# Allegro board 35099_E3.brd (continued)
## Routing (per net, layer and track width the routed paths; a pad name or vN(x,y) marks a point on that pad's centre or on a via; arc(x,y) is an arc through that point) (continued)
P1_7_RST: length 171.8
  TOP w0.114: R144.3 v1(89.9,94.64) 92.18,94.64 TP42.1
  TOP w0.508: U32.4 v1(146.57,15.73)
  L3_IN1 w0.114: v1(76.71,25.53) 86.92,15.31 146.15,15.31 v1(146.57,15.73)
  L4_IN2 w0.114: v1(76.71,25.53) 77.92,26.74 84.62,26.74 98.39,40.51 99.31,40.51 102,43.2 102,50.95 98.44,54.51 98.44,69.27 102.21,73.04 102.21,74.69 101.27,75.64 99.1,75.64 94.11,80.62 94.11,89.58 92.61,91.08 92.61,91.94 v1(89.9,94.64)
P1_8: length 111.7
  TOP w0.114: v1(59.2,40.12) 44.92,40.12 J27.8 ; U18.B5 91.18,68.81 91.18,69.11 89.36,70.93 88.57,70.93 86.87,72.62 v1(86.87,73.13)
  L3_IN1 w0.114: v1(86.87,73.13) 76.28,73.13 73.83,70.68 64.2,70.68 50.67,57.15 34.95,57.15 J27.8
  BOTTOM w0.114: R209.1 R231.1 63.37,35.17 63.26,35.29 63.26,36.07 v1(59.2,40.12)
P1_9: length 78.8
  TOP w0.114: v1(72.9,73.18) 84.26,73.18 88.92,68.52 U18.B1 ; J28.1 27.43,60.29 29.11,61.97 43.65,61.97 45.05,63.36 50.66,63.36 52.98,65.67 52.98,70.01 v1(52.84,70.14)
  L3_IN1 w0.114: v1(72.9,73.18) 59.36,73.18 56.33,70.14 v1(52.84,70.14)
P1_10_MCLK: length 173.2
  TOP w0.114: U35.8 52.6,96.54 52.32,96.27 v1(52.32,95.81) 49.61,95.81 49.29,96.12 R403.1 ; v1(106.63,65) 105.1,65 104.62,64.52 U18.K16 ; TP8.1 v1(81.64,92.86)
  L3_IN1 w0.114: v1(81.64,92.86) 87.95,86.54 103.49,86.54 v1(103.51,86.53) ; J27.6 39.47,56.59 52.14,56.59 65.74,70.19 94.34,70.19 94.99,69.54 100.48,69.54 105.02,65 v1(106.63,65)
  L4_IN2 w0.114: v1(106.63,65) 106.64,65.02 106.64,83.39 v1(103.51,86.53)
  BOTTOM w0.114: v1(52.32,95.81) 52.73,95.4 65.08,95.4 67.62,92.86 v1(81.64,92.86)
P1_11_SPI_CLK: length 22.5
  TOP w0.114: U18.L2 89.71,63.77 86.07,63.77 85.12,62.82 72.35,62.82 72.03,62.51 72.03,59.68 71.43,59.08 R385.2
P1_11_SPI_CLK_A: length 161.5
  TOP w0.114: v1(64.67,62.09) 65.05,62.48 65.05,85.31 68.64,88.9 107.45,88.9 109.88,91.33 109.88,98.8 112.68,101.6 U4.13 ; R385.3 71.18,61.43 v1(71.14,61.46)
  L3_IN1 w0.114: v1(23.37,26.04) 22.86,26.54 22.86,34.54 23.5,35.18 33.02,35.18 54.23,56.39 56.52,56.39 61.78,61.66 70.95,61.66 v1(71.14,61.46)
  BOTTOM w0.114: R114.2 v1(23.37,26.04) ; v1(71.14,61.46) 70.51,62.09 v1(64.67,62.09)
P1_12_SPI_MISO: length 19.9
  TOP w0.114: U18.M2 86.17,63.52 85.22,62.58 74.9,62.58 73.81,61.49 73.81,59.68 73.21,59.08 R386.2
P1_12_SPI_MISO_A: length 152.8
  TOP w0.114: R386.3 72.95,61.43 v1(72.92,61.46) ; U26.7 110.94,96.21 110.37,95.64 110.37,91.08 107.72,88.42 68.84,88.42 65.53,85.11 65.53,63.9 v1(66.19,63.24)
  L3_IN1 w0.114: v1(33.02,33.91) 33.02,34.67 54.23,55.88 56.9,55.88 62.04,61.02 72.48,61.02 v1(72.92,61.46)
  BOTTOM w0.114: v1(33.02,33.91) 28.45,29.34 R112.2 ; v1(66.19,63.24) 66.82,62.6 71.78,62.6 v1(72.92,61.46)
P1_13_SPI_MOSI: length 14.6
  TOP w0.114: R387.2 76.82,59.08 79.84,62.1 85.42,62.1 86.35,63.02 U18.N1
P1_13_SPI_MOSI_A: length 162.3
  TOP w0.114: U4.11 113.5,102.6 113.49,102.61 112.06,102.61 108.98,99.53 108.98,91.17 107.2,89.39 68.44,89.39 64.14,85.08 64.14,66.27 63.14,65.27 63.14,60.42 v1(62.04,59.31) ; R387.3 76.51,61.55 v1(76.48,61.59)
  L3_IN1 w0.114: v1(23.37,30.99) 24.13,31.75 42.55,31.75 56.52,45.72 56.52,53.79 v1(62.04,59.31) 63.26,60.54 75.43,60.54 v1(76.48,61.59)
  BOTTOM w0.114: R111.2 v1(23.37,30.99)
P1_14_SPI_SS0: length 18.2
  TOP w0.114: U18.N2 89.71,63.28 86.27,63.28 85.32,62.34 76.31,62.34 75.59,61.62 75.59,59.68 74.99,59.08 R388.2
P1_14_SPI_SS0_A: length 177.3
  TOP w0.114: R388.3 74.73,61.43 v1(74.7,61.46) ; U4.14 112.56,101.1 110.13,98.67 110.13,91.18 107.62,88.66 68.74,88.66 65.29,85.21 65.29,61.7 59.22,55.63 58.17,55.63 56.52,53.98 56.52,47.24 v1(53.47,44.19)
  L3_IN1 w0.114: 53.47,44.19 53.47,51.31 57.15,54.99 57.15,55.34 62.59,60.78 74.02,60.78 v1(74.7,61.46) ; 53.47,44.19 v1(53.47,44.19) ; 53.47,44.19 42.17,32.89 24.77,32.89 v1(23.37,34.29)
  BOTTOM w0.114: R109.2 v1(23.37,34.29)
P1_15: length 72.3
  TOP w0.114: R86.2 JP13.3 137.44,51.15 SW5.6 ; v1(84.42,61.4) 84.87,61.86 85.52,61.86 86.43,62.77 90.21,62.77 U18.N3
  L3_IN1 w0.114: v1(84.42,61.4) 84.99,61.98 87.44,61.98 88.83,60.59 97.11,60.59 98.46,59.24 98.46,57.21 103.85,51.82 109.35,51.82 v1(111.38,53.85)
  L4_IN2 w0.114: JP13.3 129.88,54.7 129.41,54.23 116.84,54.23 116.46,53.85 v1(111.38,53.85)
P1_16: length 82.6
  TOP w0.114: R87.2 JP13.1 143.76,53.46 143.76,49.28 143,48.51 140.72,48.51 139.86,49.37 SW5.5 ; U18.M4 v2(90.47,63.52)
  L3_IN1 w0.114: v1(87.02,61.54) 87.54,61.54 88.7,60.38 96.98,60.38 98.08,59.28 98.08,55.46 102.18,51.36 v1(112.83,51.36)
  L4_IN2 w0.114: JP13.1 140.98,53.16 125.98,53.16 123.74,50.93 113.27,50.93 v1(112.83,51.36)
  BOTTOM w0.114: v1(87.02,61.54) 89,63.52 v2(90.47,63.52)
P1_17: length 66.2
  TOP w0.114: U18.N4 v2(90.97,62.52) ; SW5.4 142.4,52.83 141.02,54.2 141.02,55.57 v1(140.46,56.13) R88.2
  L3_IN1 w0.114: v2(90.97,62.52) 90.99,62.52 91.97,61.54 96.85,61.54 99.1,59.29 99.1,58.13 101.47,55.75 v1(109.73,55.75)
  L4_IN2 w0.114: v1(140.46,56.13) 141.22,55.37 141.22,54.23 140.41,53.41 125.42,53.41 124,51.99 112.47,51.99 109.73,54.74 v1(109.73,55.75)
P1_18_OSPI_CLK0: length 16.3
  TOP w0.114: v1(94.47,54.43) 94.47,58.4 93.73,59.14 93.73,61.27 U18.T9 ; R245.1 v1(89.36,54.32)
  L3_IN1 w0.114: v1(89.36,54.32) 88.29,54.32 88.14,54.17 88.14,54 88.3,53.84 90.54,53.84 91.13,54.43 v1(94.47,54.43)
P1_19_OSPI_SSEL0: length 27.7
  TOP w0.114: v1(90.53,59.31) 90.97,59.75 U18.T4 ; R247.1 R240.2 83.76,47.31 v1(84.2,47.75) ; R248.1 v1(80.53,58.31)
  L3_IN1 w0.114: v1(80.53,58.31) 81.53,59.31 v1(90.53,59.31)
  L4_IN2 w0.114: v1(84.2,47.75) 80.53,51.42 v1(80.53,58.31)
P1_20_OSPI_D0: length 16.5
  TOP w0.114: R243.2 v1(89.36,53.32) ; v1(92.17,53.37) 92.17,55.37 91.09,56.45 91.09,57.89 91.21,58.02 91.21,61.27 U18.T5
  L3_IN1 w0.114: v1(89.36,53.32) 87.67,53.32 87.5,53.15 87.5,52.99 87.67,52.82 91.62,52.82 v1(92.17,53.37)
P1_21_OSPI_D1: length 15.8
  TOP w0.114: R417.2 v1(89.36,51.32) ; U18.U5 91.47,57.94 91.33,57.79 91.33,56.55 92.61,55.27 92.61,52.92 92.33,52.64 v1(92.33,52.07)
  L3_IN1 w0.114: v1(92.33,52.07) 92.33,51.15 92.02,50.83 88.98,50.83 88.83,50.98 88.83,51.15 89,51.32 v1(89.36,51.32)
P1_22_OSPI_D2: length 18
  TOP w0.114: v1(92.03,56.81) 91.83,57.02 91.83,57.61 91.97,57.76 U18.P6 ; v1(81.53,58.31) R418.2
  L3_IN1 w0.114: v1(81.53,58.31) 82.03,57.81 85.96,57.81 86.96,56.81 v1(92.03,56.81)
P1_23_OSPI_D3: length 16.4
  TOP w0.114: R419.2 v1(85.53,57.31)
  TOP w0.127: U18.P7 92.22,62.27 92.22,57.25 92.84,56.63 v1(92.84,56.25)
  L3_IN1 w0.114: v1(85.53,57.31) 86.59,56.25 88.44,56.25 88.54,56.15 88.54,56.13 88.64,56.03 88.78,56.03 88.89,56.13 88.89,56.15 88.99,56.25 89.13,56.25 89.23,56.15 89.23,55.93 89.33,55.83 89.47,55.83 89.57,55.93 89.57,56.15 89.67,56.25 89.81,56.25 90.01,56.05 90.15,56.05 90.25,56.15 90.26,56.15 90.36,56.25 v1(92.84,56.25)
P1_24_OSPI_D4: length 17
  TOP w0.114: U18.T7 92.48,61.52 92.72,61.28 92.72,57.9 92.92,57.7 v1(92.92,57.52) ; R244.2 v1(83.53,58.31)
  L3_IN1 w0.114: v1(92.92,57.52) 91.46,57.52 91.36,57.62 91.36,57.74 91.26,57.84 91.12,57.84 91.02,57.74 91.02,57.62 90.92,57.52 90.77,57.52 90.67,57.62 90.67,57.9 90.57,58 90.43,58 90.33,57.9 90.33,57.62 90.23,57.52 90.09,57.52 89.99,57.62 89.99,57.76 89.89,57.86 89.75,57.86 89.65,57.76 89.65,57.62 89.55,57.52 89.4,57.52 89.3,57.62 89.3,57.76 89.2,57.86 89.06,57.86 88.96,57.76 88.96,57.62 88.86,57.52 88.72,57.52 88.62,57.62 88.27,57.62 88.17,57.52 88.03,57.52 87.93,57.62 87.59,57.62 87.49,57.52 86.82,57.52 86.03,58.31 v1(83.53,58.31)
P1_25_OSPI_D5: length 17.5
  TOP w0.114: v1(93.29,53.33) 93.29,56.53 92.48,57.34 92.48,61.02 U18.U7 ; R420.2 v1(89.36,52.32)
  L3_IN1 w0.114: v1(89.36,52.32) 87.58,52.32 87.45,52.19 87.45,51.93 87.57,51.82 91.44,51.82 92.95,53.33 v1(93.29,53.33)
P1_26_OSPI_D6: length 16.7
  TOP w0.114: R421.2 v1(89.36,50.32) ; v1(93.95,52.35) 94.03,52.43 94.03,57.55 93.22,58.36 93.22,61.64 92.84,62.02
  TOP w0.127: 92.84,62.02 U18.R7
  L3_IN1 w0.114: v1(93.95,52.35) 91.92,50.32 v1(89.36,50.32)
P1_27_OSPI_D7: length 16.4
  TOP w0.114: v1(93.34,50.93) 93.34,52.7 93.73,53.08 93.73,57.51 92.97,58.27 92.97,61.52 U18.T8 ; R422.2 89.19,49.32 89.19,49.31 v1(89.36,49.31)
  L3_IN1 w0.114: v1(89.36,49.31) 89.37,49.31 91.73,49.31 v1(93.34,50.93)
P1_28_OSPI_DQS: length 16
  TOP w0.114: v1(94.02,58.24) 93.47,58.78 U18.U9 ; R246.1 v1(82.53,58.31)
  L3_IN1 w0.114: v1(82.53,58.31) 83.15,58.93 89.42,58.93 89.68,58.67 93.59,58.67 v1(94.02,58.24)
P1_29_OSPI_B_SCK: length 49.5
  TOP w0.114: R352.1 61.54,44.87 62.21,44.2 78.74,44.2 80.64,46.1 v1(80.64,47.24) ; U18.U3 90.47,60.65 89.85,60.03 89.85,57 91.49,55.37 91.49,49.65 91.69,49.44 v1(91.69,48.64)
  L3_IN1 w0.114: v1(91.69,48.64) 91.69,48.13 90.34,46.78 81.11,46.78 v1(80.64,47.24)
P1_30_SD0_CLK: length 50.1
  TOP w0.114: v1(97.61,50.61) 96.03,52.19 96.03,57.52 94.21,59.34 94.21,62.28 U18.P10 ; R302.2 v1(118.51,33.77)
  L3_IN1 w0.114: v1(97.61,50.61) 99.37,50.61 103.35,46.64 103.35,46.48 103.17,46.3 103.17,46.13 103.33,45.97 103.49,45.97 103.67,46.15 103.83,46.15 103.99,45.99 103.99,45.83 103.81,45.65 103.81,45.49 103.97,45.33 104.14,45.33 104.32,45.51 104.48,45.51 104.64,45.35 104.64,45.18 104.46,45 104.46,44.84 104.62,44.68 104.78,44.68 104.96,44.86 105.13,44.86 105.29,44.7 105.29,44.54 105.11,44.36 105.11,44.19 105.27,44.03 105.43,44.03 105.61,44.21 105.77,44.21 105.93,44.05 105.93,43.89 105.75,43.71 105.75,43.55 105.91,43.39 106.08,43.39 106.26,43.57 106.42,43.57 106.58,43.41 106.58,43.24 106.4,43.06 106.4,42.9 106.56,42.74 106.72,42.74 106.9,42.92 107.07,42.92 107.23,42.76 107.23,42.6 107.05,42.42 107.05,42.26 107.21,42.09 107.37,42.09 107.55,42.27 107.71,42.27 107.87,42.11 107.87,41.95 107.69,41.77 107.69,41.61 107.85,41.45 108.02,41.45 108.2,41.63 108.36,41.63 108.52,41.47 108.52,41.3 108.34,41.12 108.34,40.96 108.5,40.8 108.66,40.8 108.84,40.98 109.01,40.98 109.17,40.82 109.17,40.66 108.99,40.48 108.99,40.32 109.15,40.15 109.31,40.15 109.49,40.34 109.65,40.34 109.81,40.17 109.81,40.01 109.63,39.83 109.63,39.67 109.79,39.51 109.96,39.51 110.14,39.69 110.3,39.69 116.21,33.77 v1(118.51,33.77)
P1_31_SD0_CMD: length 52.2
  TOP w0.114: v1(95.53,55.57) 95.53,57.69 93.97,59.24 93.97,61.52 U18.R9 ; v1(126.26,34.54) 126.26,34.21 126.7,33.77 R303.2
  L3_IN1 w0.114: v1(126.26,34.54) 126.26,37.39 120.24,43.41 119.27,43.41 119.16,43.29 119.16,43.14 119.05,43.03 118.82,43.03 118.7,43.14 118.7,43.29 118.59,43.41 118.36,43.41 118.25,43.29 118.25,43.14 118.13,43.03 117.9,43.03 117.79,43.14 117.79,43.29 117.67,43.41 117.45,43.41 117.33,43.29 117.33,43.14 117.22,43.03 116.99,43.03 116.87,43.14 116.87,43.29 116.76,43.41 116.53,43.41 116.42,43.29 116.42,43.14 116.3,43.03 116.07,43.03 115.96,43.14 115.96,43.29 115.85,43.41 115.62,43.41 115.5,43.29 115.5,43.14 115.39,43.03 115.16,43.03 115.05,43.14 115.05,43.29 114.93,43.41 110.39,43.41 108.71,45.09 106.38,45.09 95.9,55.57 v1(95.53,55.57)
P2_0_SD0_D0: length 51.9
  TOP w0.114: 95.11,62.02 95.22,61.91 95.22,59.7 98.12,56.8 98.12,49.99 97.38,49.25 v1(96.49,49.25) ; v1(113.92,33.02) 114.67,33.77 R301.2
  TOP w0.127: 95.11,62.02 U18.R11
  L3_IN1 w0.114: v1(113.92,33.02) 113.54,32.64 108.53,32.64 107.8,33.38 107.8,33.54 107.94,33.68 107.94,33.84 107.78,34 107.62,34 107.47,33.86 107.31,33.86 107.15,34.02 107.15,34.18 107.29,34.33 107.29,34.49 107.13,34.65 106.97,34.65 106.83,34.51 106.67,34.51 106.5,34.67 106.5,34.83 106.65,34.97 106.65,35.14 106.49,35.3 106.32,35.3 106.18,35.15 106.02,35.15 105.86,35.32 105.86,35.48 106,35.62 106,35.78 105.84,35.94 105.68,35.94 105.53,35.8 105.37,35.8 105.21,35.96 105.21,36.12 105.35,36.27 105.35,36.43 105.19,36.59 105.03,36.59 104.89,36.45 104.73,36.45 104.56,36.61 104.56,36.77 104.71,36.91 104.71,37.07 104.55,37.24 104.38,37.24 104.24,37.09 104.08,37.09 103.92,37.25 103.92,37.42 104.06,37.56 104.06,37.72 103.9,37.88 103.74,37.88 103.59,37.74 103.43,37.74 103.27,37.9 103.27,38.06 103.41,38.21 103.41,38.37 103.25,38.53 103.09,38.53 102.95,38.39 102.79,38.39 102.63,38.55 102.63,38.71 102.77,38.85 102.77,39.01 102.61,39.18 102.44,39.18 102.3,39.03 102.14,39.03 101.98,39.19 101.98,39.36 102.12,39.5 102.12,39.66 101.96,39.82 101.8,39.82 101.66,39.68 101.49,39.68 101.33,39.84 101.33,40 101.48,40.15 101.48,40.31 101.31,40.47 101.15,40.47 101.01,40.33 100.85,40.33 100.69,40.49 100.69,40.65 100.83,40.79 100.83,40.95 100.67,41.12 100.51,41.12 100.36,40.97 100.2,40.97 100.04,41.13 100.04,41.3 100.18,41.44 100.18,41.6 100.02,41.76 99.86,41.76 99.72,41.62 99.55,41.62 98.93,42.24 98.93,46.81 v1(96.49,49.25)
P2_1_SD0_D1: length 50.2
  TOP w0.114: v1(97.25,52.27) 97.25,56.99 94.73,59.51 94.73,61.27 U18.T11 ; v1(111.9,33.2) 112.48,33.77 R300.2
  L3_IN1 w0.114: v1(111.9,33.2) 111.28,33.83 109.45,33.83 106.93,36.35 106.93,36.51 107.29,36.87 107.29,37.03 107.13,37.19 106.97,37.19 106.61,36.83 106.45,36.83 106.29,36.99 106.29,37.16 106.65,37.52 106.65,37.68 106.48,37.84 106.32,37.84 105.96,37.48 105.8,37.48 105.64,37.64 105.64,37.8 106,38.16 106,38.32 105.84,38.49 105.68,38.49 105.32,38.13 105.15,38.13 104.99,38.29 104.99,38.45 105.35,38.81 105.35,38.97 105.19,39.13 105.03,39.13 104.67,38.77 104.51,38.77 104.35,38.93 104.35,39.1 104.71,39.46 104.71,39.62 104.54,39.78 104.38,39.78 104.02,39.42 103.86,39.42 103.7,39.58 103.7,39.74 104.06,40.1 104.06,40.26 103.9,40.43 103.74,40.43 103.38,40.07 103.22,40.07 103.05,40.23 103.05,40.39 103.41,40.75 103.41,40.91 103.25,41.07 103.09,41.07 102.73,40.71 102.57,40.71 102.41,40.87 102.41,41.04 102.77,41.4 102.77,41.56 102.6,41.72 102.44,41.72 102.08,41.36 101.92,41.36 101.76,41.52 101.76,41.68 102.12,42.04 102.12,42.2 101.96,42.37 101.8,42.37 101.44,42.01 101.28,42.01 101.11,42.17 101.11,42.33 101.47,42.69 101.47,42.85 101.31,43.01 101.15,43.01 100.79,42.65 100.63,42.65 99.57,43.71 99.57,47.45 96.98,50.04 96.98,52 v1(97.25,52.27)
P2_2_SD0_D2: length 51.2
  TOP w0.114: U18.U11 94.47,59.43 96.6,57.3 v1(96.6,55.95) ; R305.2 v1(130.84,33.77)
  L3_IN1 w0.114: v1(96.6,55.95) 97.06,55.95 104.4,48.62 112.04,48.62 114.43,46.23 119.3,46.23 130,35.53 130,34.61 v1(130.84,33.77)
P2_3_SD0_D3: length 49.9
  TOP w0.114: R304.2 129.07,33.77 128.52,34.32 v1(128.52,34.54) ; U18.T12 94.97,59.61 97.69,56.89 v1(97.69,54.68)
  L3_IN1 w0.114: v1(97.69,54.68) 106.19,46.18 113.44,46.18 114.76,44.86 119.84,44.86 128.93,35.76 128.93,34.95 v1(128.52,34.54)
P2_4_SD0_WR_PRT: length 68.5
  TOP w0.114: U18.T13 95.85,61.15 95.85,59.76 96.98,58.62 99.6,56 v1(99.6,55.45) TP21.1 ; R307.2 122.95,33.84 v1(122.32,34.47)
  L4_IN2 w0.114: v1(122.32,34.47) 122.32,34.02 124.24,32.09 124.24,28.65 122.46,26.87 109.38,26.87 99.48,36.78 99.48,37.92 103.79,42.24 103.79,51.25 v1(99.6,55.45)
P2_5_SD0_D4: length 10.7
  TOP w0.114: TP24.1 98.36,52.6 98.36,56.9 96.6,58.66 95.47,59.79 U18.U13
P2_6_SD0_D5: length 8.9
  TOP w0.114: U18.U15 96.47,59.81 100.66,55.62 100.66,55.4 TP25.1
P2_7_SD0_D6: length 12.1
  TOP w0.114: TP26.1 103.26,53.05 102.91,53.41 102.91,54.31 102.08,55.13 101.49,55.13 97.3,59.33 97.3,60.51 96.97,60.83 U18.U16
P2_8_SD0_D7: length 13.7
  TOP w0.114: TP14.1 105.3,54.34 104.02,55.62 101.69,55.62 97.78,59.53 97.78,60.72 U18.U17
P2_9_SD0_CD: length 70.4
  TOP w0.114: J32.10 v1(125.38,31.57) 125.38,33.21 R310.2 ; TP22.1 v1(101.12,53.04) 100.42,53.74 100.42,55.52 96.09,59.86 96.09,61.41 U18.R13
  L4_IN2 w0.114: v1(101.12,53.04) 103.17,50.99 103.17,42.5 98.85,38.18 98.85,36.52 109.12,26.24 122.72,26.24 125.38,28.9 v1(125.38,31.57)
P2_10_SD0_RST_N: length 42.5
  TOP w0.114: v1(120.54,34.47) 121.17,33.84 R306.2 ; v2(96.83,60.02) 96.83,60.65 96.72,60.76 96.72,61.27 U18.T15
  L3_IN1 w0.114: v2(96.83,60.02) 95.09,58.27 95.09,55.01 96.42,53.68 97.16,53.68 114.44,36.4 115.75,36.4 117.67,34.47 v1(120.54,34.47)
P2_11_SD0_VOLT: length 96
  TOP w0.102: U18.T16 96.97,61.4 97.22,61.15 97.22,60.92
  TOP w0.114: v1(103.78,53.16) TP23.1 102.72,55.38 101.59,55.38 97.54,59.43 97.54,60.61 97.22,60.92
  L4_IN2 w0.114: v1(103.78,53.16) 105.79,55.17 105.79,63.36 107.32,64.89 107.32,65.24 107.52,65.44 107.52,65.8 107.32,66 107.32,83.95 107.32,83.96 102.86,88.42 96.41,88.42 93.38,91.45 93.38,92.39 91.19,94.59 91.19,105.91 88.85,108.24 86.5,108.24 85.34,109.4 85.34,114.5 87.71,116.87 87.71,118.54 J1.1
P2_12: length 186.3
  TOP w0.114: v1(85.13,10.74) 85.47,11.09 85.47,37.85 v1(82.17,41.15) ; R131.2 TP33.1 ; U18.T3 90.22,61.27 90.22,60.74 88.53,59.05 88.53,58.7 v1(88.78,58.46)
  TOP w0.152: U24.13 v1(143.13,7.44) 143.13,6.13 TP33.1
  L3_IN1 w0.114: v1(143.13,7.44) 140.98,9.6 86.27,9.6 v1(85.13,10.74)
  L4_IN2 w0.114: 88.77,58.46 86.11,61.12 86.11,76.81 87.36,78.06 87.36,83.61 85.85,85.12 85.85,95.54 89.51,99.2 89.51,104.11 84.53,109.09 84.53,116.64 J1.4 ; 88.77,58.46 v1(88.78,58.46) ; 88.77,58.46 86.49,56.18 86.49,46.51 82.17,42.19 v1(82.17,41.15)
P2_13: length 64.9
  TOP w0.114: U18.T1 88.27,60.33 v1(88.03,60.33)
  L4_IN2 w0.114: J1.2 84.94,115.93 84.94,109.27 89.9,104.31 89.9,98 86.23,94.33 86.23,85.29 87.6,83.93 87.6,77.79 86.35,76.55 86.35,62.92 88.03,61.24 v1(88.03,60.33)
P2_14: length 71.3
  TOP w0.114: v1(73.66,72.69) 84.4,72.69 89.08,68.02 U18.C1
  L4_IN2 w0.114: J1.9 77.46,118.63 77.46,116.84 79.65,114.64 79.65,108.5 70.73,99.57 70.73,84.74 73.41,82.06 73.41,72.94 v1(73.66,72.69)
P2_15: length 71.5
  TOP w0.114: U18.E2 89.71,66.77 83.34,66.77 83.04,66.46 v1(75.32,66.46)
  L4_IN2 w0.114: v1(75.32,66.46) 75.32,66.87 74.48,67.71 74.48,82.83 71.62,85.68 71.62,99.99 80.24,108.61 80.24,115.85 J1.8
P2_16_PDM_CLK01: length 23.3
  TOP w0.114: U18.R1 88.74,62.02 87.13,60.41 87.13,58.02 90.28,54.87 90.28,48.9 86.8,45.41 86.8,44.14 87.61,43.33 R379.2
P2_17_PDM_CLK23: length 20.4
  TOP w0.114: U18.U1 87.61,59.17 87.61,58.22 90.77,55.07 90.77,48.44 90.26,47.93 90.26,44.23 91.16,43.33 R389.2
P2_17_PDM_CLK23_A: length 37.1
  TOP w0.114: J31.5 96.22,14.48 94.11,14.48 93.6,13.97 93.6,12.95 93.03,12.39 91.75,12.39 91.24,12.9 R389.3
P2_18_PDM_CLK45: length 22.7
  TOP w0.114: R390.2 89.38,43.33 88.7,44.01 88.7,46.91 90.53,48.74 90.53,54.97 87.37,58.12 87.37,60.31 88.83,61.77 89.72,61.77 U18.R2
P2_18_PDM_CLK45_A: length 34.4
  TOP w0.114: J31.7 93.59,12.15 91.36,12.15 90.81,12.7 90.81,40.47 R390.3
P2_19_PDM_CLK67: length 21.3
  TOP w0.114: U18.T2 89.72,61.27 89.72,60.92 87.86,59.06 87.86,58.32 91.01,55.17 91.01,48.28 92.2,47.09 92.2,44.07 92.94,43.33 R384.2
P2_19_PDM_CLK67_A: length 28.8
  TOP w0.114: J31.9 93.02,14.12 R384.3
P2_20_PDM_DATA01: length 21.3
  TOP w0.114: U18.U2 89.97,60.83 88.1,58.96 88.1,58.42 91.25,55.27 91.25,48.38 93.78,45.86 93.78,44.27 94.72,43.33 R380.2
P2_21_PDM_DATA23: length 21.8
  TOP w0.114: R393.2 96.5,43.33 95.65,44.17 95.65,45.82 91.73,49.75 91.73,55.47 90.09,57.1 90.09,59.93 90.72,60.56 90.72,61.62 90.47,61.87 U18.R3
P2_21_PDM_DATA23_A: length 34.4
  TOP w0.114: v1(96.58,16.89) R393.1
  BOTTOM w0.114: J31.6 96.09,12.06 96.09,13.76 94.11,15.75 94.11,16.26 94.74,16.89 v1(96.58,16.89)
P2_22_PDM_DATA45: length 27.4
  TOP w0.114: U18.P3 88.9,62.52 86.89,60.51 86.89,57.92 90.04,54.77 90.04,49 89.32,48.27 85.82,48.27 85.02,47.47 85.02,44.14 85.83,43.33 R391.2
P2_22_PDM_DATA45_A: length 39.4
  TOP w0.114: J31.8 93.7,9.72 89.44,9.72 88.27,10.9 88.27,39.45 R391.3
P2_23_PDM_DATA67: length 23
  TOP w0.114: R392.2 98.27,43.33 97.41,44.2 97.41,47.6 96.59,48.42 95.24,48.42 92.85,50.8 92.85,55.37 91.57,56.65 91.57,57.69 91.72,57.84 91.72,62.28 U18.P5
P2_23_PDM_DATA67_A: length 35.6
  TOP w0.114: v1(98.35,17.53) R392.3
  BOTTOM w0.114: J31.10 93.47,12.03 93.47,16.26 94.74,17.53 v1(98.35,17.53)
P2_24_SWO: length 50.3
  TOP w0.114: v1(100.35,97.02) 100.05,96.71 U7.12 ; v1(108.26,64.33) 107.78,63.85 107.29,63.85 107.21,63.77 97.23,63.77 U18.L16
  L4_IN2 w0.114: v1(108.26,64.33) 107.81,64.77 107.81,65.05 108,65.24 108,66 107.81,66.19 107.81,84.54 107.87,84.6 107.87,85.16 107.81,85.22 107.81,86.3 107.78,86.34 107.78,86.67 108.04,86.94 108.04,87.3 107.78,87.57 107.78,90.24 108.06,90.52 108.06,90.88 107.78,91.17 107.78,91.25 102,97.02 v1(100.35,97.02)
P2_25_SWD_CLK: length 49.3
  TOP w0.114: v1(107.47,64.35) 107.15,64.35 106.82,64.02 U18.L17 ; U7.4 96.96,95.51 96.34,94.89 v1(96.34,94.02)
  L4_IN2 w0.114: v1(96.34,94.02) 97.15,93.21 100.57,93.21 107.57,86.2 107.57,85.12 107.63,85.06 107.63,84.7 107.57,84.64 107.57,66.09 107.76,65.9 107.76,65.34 107.57,65.15 107.57,64.46 v1(107.47,64.35)
P2_26_SWDIO: length 136.2
  TOP w0.114: v1(105.54,64.54) 105.28,64.28 96.72,64.28 U18.L15 ; v1(100.59,105.96) 98.97,105.96 96.9,108.03 JP19.1 98.53,111.3 107.98,111.3 v1(110.53,113.86) 110.74,114.07 J2.2 ; v1(101.26,87.05) 101.14,87.18 73.08,87.18 v1(71.25,85.35) J19.2 ; SH14.1 v1(75.77,107.95)
  L3_IN1 w0.114: v1(75.77,107.95) 82.07,107.95 82.57,108.45 95.68,108.45 JP19.1
  L4_IN2 w0.114: v1(105.54,64.54) 105.54,65.9 105.98,66.35 105.98,81.73 101.26,86.46 v1(101.26,87.05)
  BOTTOM w0.114: v1(101.26,87.05) 101.26,93.14 101.49,93.36 101.49,100.09 100.38,101.2 100.38,105.75 v1(100.59,105.96) ; D13.5 110.15,115.42 110.53,115.04 v1(110.53,113.86) ; R105.2 v1(71.25,85.35)
P2_27_USB1_OVERCURRENTN: length 76.3
  TOP w0.114: U13.A2 126.69,67.99 v1(125.76,67.99) ; U18.M14 107.41,63.52 v1(107.6,63.33) 108.74,63.33 111.1,65.7 111.1,73.81 109.69,75.22 107.14,75.22 104.31,78.05 97.86,78.05 R133.2
  L3_IN1 w0.114: v1(107.6,63.33) 122.51,63.33 125.76,66.57 v1(125.76,67.99)
P2_28_USB1_PWRENA: length 64.6
  TOP w0.114: v1(127.37,68.01) 130.8,71.44 Q1.1 ; R383.2 v1(102.02,82.19) ; U18.N15 96.73,63.28 106.62,63.28 v1(107.22,62.68)
  L3_IN1 w0.114: v1(127.37,68.01) 127.37,66.91 123.15,62.7 107.24,62.7 v1(107.22,62.68)
  L5_PWR w0.114: v1(107.22,62.68) 106.33,63.58 106.33,64.51 105.45,65.4 105.45,78.76 v1(102.02,82.19)
P2_29_I3C0_SCL: length 204.7
  TOP w0.114: v1(83.19,33.15) 81.66,33.15 R423.1 ; v1(98.68,90.21) 98.18,89.7 82.29,89.7 v1(82.17,89.83) 69.71,89.83 68.3,91.24 49.28,91.24 TP7.1 ; TP7.1 v1(48.64,90.7) ; TP7.1 47.64,92.87 47.64,94.42 47.85,94.63 47.85,99.11 49.85,101.11 R406.1 50.91,100.77 52.01,100.77 R409.2 U36.1 ; U18.N17 97.7,62.79 102.71,62.79 v1(102.76,62.84) ; R413.2 101.24,84.51 J18.1
  TOP w0.152: v1(49.71,76.67) 49.61,76.58 46.34,76.58 U12.A6 ; v1(49.44,64.69) 47.31,64.69 45.95,66.06 U17.A6
  L4_IN2 w0.114: v1(102.76,62.84) 102.76,63.82 105.5,66.56 105.5,80.24 J18.1 ; v1(82.17,89.83) 82.17,79.38 84.96,76.58 84.96,64.92 83.68,63.64 83.68,59.83 84.09,59.42 84.09,49.76 84.71,49.15 84.71,45.48 80.52,41.29 80.52,36.7 83.19,34.04 v1(83.19,33.15)
  L4_IN2 w0.152: v1(48.64,90.7) 49.71,89.64 v1(49.71,76.67) 49.71,64.96 v1(49.44,64.69)
  BOTTOM w0.114: J18.1 99.36,86.38 99.36,89.53 v1(98.68,90.21)
P2_30_I3C0_SDA: length 159.7
  TOP w0.114: J18.2 R414.2 R118.1 R405.1 ; v1(104.34,62.44) 104.02,62.13 102.51,62.13 102.36,62.27 97.22,62.27 U18.P16 ; v1(96.98,90.19) 96.74,90.42 70.06,90.42 68.75,91.74 50.85,91.74 v1(49.4,93.19) TP6.1 48.11,94.48 48.11,97.68 49.37,98.93 59.02,98.93 59.71,99.62 59.71,101.43 59.28,101.85 58.56,101.85 R410.2 U36.8
  TOP w0.152: U17.B6 46,65.6 46.01,65.6 47.66,63.95 v1(49.43,63.95) ; U12.B6 46.35,76.17 v1(50.32,76.17)
  L4_IN2 w0.114: J18.2 98.94,86.27 100.85,86.27 105.74,81.38 105.74,66.46 104.34,65.06 v1(104.34,62.44)
  L4_IN2 w0.152: v1(49.4,93.19) 50.32,92.27 v1(50.32,76.17) 50.32,64.83 v1(49.43,63.95)
  BOTTOM w0.114: J18.2 98.91,86.25 98.91,88.26 v1(96.98,90.19)
P2_31_I3C0_PUR: length 29.6
  TOP w0.114: R118.2 J18.3 ; v1(86.62,82.97) 86.27,82.97 86.06,82.76 86.06,75.31 88.03,73.35 88.03,72.49 88.87,71.65 89.72,71.65 91.97,69.4 U18.B6
  BOTTOM w0.114: J18.3 93.74,83.62 87.27,83.62 v1(86.62,82.97)
PDM_CLK01_EXT: length 41.7
  TOP w0.114: J31.3 98.4,11.88 89.46,11.88 88.75,12.6 88.75,40.75 R379.3
PDM_CLK01_ONBOARD: length 151.3
  TOP w0.114: v1(98.96,39.49) 99.31,39.13 99.31,34.5 105.05,28.76 105.05,8.71 104.52,8.18 103.78,8.18 103.24,7.65 U41.4 103.24,7.23 102.87,6.86 100.2,6.86 98.17,8.89 57.54,8.89 52.46,3.81 12.32,3.81 11.83,4.3 11.83,5.77 10.56,7.04 8.82,7.04 8.6,6.82 U40.4 ; v1(87.69,45.68) R379.1
  BOTTOM w0.114: v1(98.96,39.49) 93.88,39.49 v1(87.69,45.68)
PDM_DATA01_EXT: length 34.1
  TOP w0.114: R380.3 v1(94.8,16.26)
  BOTTOM w0.114: J31.4 98.63,12.06 98.63,14.14 96.52,16.26 v1(94.8,16.26)
PDM_DATA01_ONBOARD: length 144.6
  TOP w0.114: R380.1 v1(94.8,45.82) ; U40.1 7.78,3.92 7.89,3.81 9.25,3.81 10.14,2.92 52.7,2.92 57.91,8.13 97.92,8.13 100.22,5.83 101.72,5.83 ; 101.72,5.83 v1(101.7,5.84) ; 101.72,5.83 U41.1 ; v1(99.31,33.18) 104.14,28.34 v1(104.14,10.79)
  L3_IN1 w0.114: v1(99.31,33.18) 94.8,37.69 v1(94.8,45.82)
  BOTTOM w0.114: v1(101.7,5.84) 102.38,6.52 102.38,9.04 v1(104.14,10.79)
PIO0_7-FC1_SCK: length 37
  TOP w0.114: U18.J2 89.71,65.28 84.26,65.28 83.01,64.03 73.66,64.03 v1(72.67,65.02) ; R394.2 v1(57.67,58.67)
  L3_IN1 w0.114: v1(72.67,65.02) 70.44,62.79 61.79,62.79 v1(57.67,58.67)
PIO0_8-FC1_TXD_SCL_MISO: length 36.2
  TOP w0.114: U18.K4 85.8,64.52 84.82,63.54 70.07,63.54 v1(69.11,64.51) ; R395.2 57.67,61.34 v1(58.44,60.57)
  L3_IN1 w0.114: v1(58.44,60.57) 61.56,63.68 68.29,63.68 v1(69.11,64.51)
PIO0_10-FC1_CTS_SDA_SSELN0: length 33.7
  TOP w0.114: R396.2 84.05,43.33 83.37,44.01 83.37,46.16 85.72,48.51 89.22,48.51 89.8,49.1 89.8,54.67 86.65,57.82 86.65,59.94 v1(85.17,61.42) ; v1(85.17,64.51) 85.42,64.77 90.21,64.77 U18.J3
  L4_IN2 w0.114: v1(85.17,61.42) v1(85.17,64.51)
PIO0_14-FC2_SCK: length 46.2
  TOP w0.114: v1(69.62,72.38) 69.62,73.59 70.69,74.67 79.33,74.67 80.98,76.32 82.49,76.32 88.36,70.45 89.05,70.45 U18.A3 ; v1(56.92,64.13) 57.67,63.37 R397.2
  L3_IN1 w0.114: v1(69.62,72.38) 60.6,72.38 56.92,68.7 v1(56.92,64.13)
PIO0_31-FC4_CTS_SDA_SSELN0: length 45.6
  TOP w0.114: U18.A11 94.47,71.18 93.48,72.18 v1(93.22,72.18) ; R398.2 v1(57.67,68.32)
  L3_IN1 w0.114: v1(93.22,72.18) 90.64,72.18 89.04,73.78 76.59,73.78 73.73,70.92 60.27,70.92 v1(57.67,68.32)
QSPI_B_CS0: length 33.8
  TOP w0.114: R350.1 v1(64.54,47.82) 64.03,47.31 R364.2 ; v1(92.94,45.8) 93.02,45.71 R384.1
  L3_IN1 w0.114: v1(92.94,45.8) 92.35,45.21 67.14,45.21 v1(64.54,47.82)
  BOTTOM w0.254: R66.2 65.05,47.31 v1(64.54,47.82)
QSPI_B_DATA0: length 29.7
  TOP w0.114: R385.1 72.22,56.52 73.41,56.52 74.3,55.63 74.3,55.07 74.18,54.96 72.48,54.96 72.37,54.84 72.37,54.61 72.48,54.5 74.18,54.5 74.3,54.38 74.3,54.16 74.18,54.04 73.77,54.04 73.66,53.93 73.66,53.7 73.77,53.58 74.18,53.58 74.3,53.47 74.3,53.24 74.18,53.13 73.77,53.13 73.66,53.01 73.66,52.78 73.77,52.67 74.18,52.67 74.3,52.55 74.3,52.33 74.18,52.21 73.77,52.21 73.66,52.1 73.66,51.87 73.77,51.75 74.18,51.75 74.3,51.64 74.3,51.41 74.18,51.3 73.77,51.3 73.66,51.18 73.66,50.95 73.77,50.84 74.18,50.84 74.3,50.73 74.3,50.5 74.18,50.38 73.78,50.38 73.66,50.27 73.66,50.04 73.78,49.93 74.18,49.93 74.3,49.81 74.3,49.58 74.18,49.47 73.77,49.47 73.66,49.35 73.66,49.13 73.77,49.01 74.18,49.01 74.3,48.9 74.3,48.26 74.04,48.01 73.41,48.01 73.15,48.26 73.15,52.96 72.8,53.32 R354.1
QSPI_B_DATA1: length 34.1
  TOP w0.114: R386.1 74.68,55.83 74.68,47.88 74.29,47.5 73.41,47.5 72.26,48.64 72,48.64 71.88,48.53 71.88,47.23 71.77,47.12 71.54,47.12 71.42,47.23 71.42,48.53 71.31,48.64 71.08,48.64 70.97,48.53 70.97,47.23 70.85,47.12 70.62,47.12 70.51,47.23 70.51,48.53 70.4,48.64 70.17,48.64 70.05,48.53 70.05,47.23 69.94,47.12 69.71,47.12 69.6,47.23 69.6,48.53 69.48,48.64 69.25,48.64 69.14,48.53 69.14,47.23 69.02,47.12 68.8,47.12 68.68,47.23 68.68,48.53 68.57,48.64 68.34,48.64 68.22,48.53 68.22,47.23 68.11,47.12 67.88,47.12 67.77,47.23 67.77,48.53 67.65,48.64 67.37,48.64 R355.1
QSPI_B_DATA2: length 15.9
  TOP w0.114: R71.1 R356.1 v1(64.54,58.32) ; R387.1 76.39,57.56 v1(75.64,58.31)
  L3_IN1 w0.114: v1(64.54,58.32) 66.52,60.3 73.65,60.3 v1(75.64,58.31)
QSPI_B_DATA3: length 34.4
  TOP w0.114: R357.1 v1(66.54,58.32) ; R388.1 74.61,57.56 v1(73.85,58.32)
  L3_IN1 w0.114: v1(73.85,58.32) 73.85,59.76 73.55,60.06 73.28,60.06 73.17,59.94 73.17,58.53 73.05,58.42 72.82,58.42 72.71,58.53 72.71,59.94 72.59,60.06 72.36,60.06 72.25,59.94 72.25,58.53 72.14,58.42 71.91,58.42 71.79,58.53 71.79,59.94 71.68,60.06 71.45,60.06 71.34,59.94 71.34,58.53 71.22,58.42 70.99,58.42 70.88,58.53 70.88,59.94 70.76,60.06 70.54,60.06 70.42,59.94 70.42,58.53 70.31,58.42 70.08,58.42 69.96,58.53 69.96,59.94 69.85,60.06 69.62,60.06 69.51,59.94 69.51,58.45 69.39,58.33 69.16,58.33 69.05,58.45 69.05,59.92 68.94,60.04 68.71,60.04 68.59,59.92 68.59,58.53 68.48,58.42 68.25,58.42 68.14,58.53 68.14,59.94 68.02,60.06 67.79,60.06 67.68,59.94 67.68,58.53 67.56,58.42 67.34,58.42 67.22,58.53 67.22,59.94 67.11,60.06 66.62,60.06 65.91,59.35 65.91,58.94 v1(66.54,58.32)
QSPI_B_DATA4: length 34.9
  TOP w0.114: R389.1 91.24,47.21 v1(90.7,47.75) ; R358.1 v1(65.54,58.32)
  L3_IN1 w0.114: v1(65.54,58.32) 66.53,57.33 76.91,57.33 80.01,54.23 85.47,54.23 86.49,53.21 86.49,51.07 89.13,48.43 90.02,48.43 v1(90.7,47.75)
QSPI_B_DATA5: length 30.9
  TOP w0.114: R359.1 v1(71.24,52.32) ; v1(89.69,47.28) 89.46,47.06 R390.1
  L3_IN1 w0.114: v1(89.69,47.28) 89.49,47.28 87.55,49.22 82.29,49.22 82.17,49.1 82.17,48.76 82.06,48.64 81.83,48.64 81.71,48.76 81.71,49.1 81.6,49.22 81.37,49.22 81.26,49.1 81.26,48.76 81.14,48.64 80.91,48.64 80.8,48.76 80.8,49.1 80.69,49.22 80.46,49.22 80.34,49.1 80.34,48.76 80.23,48.64 80,48.64 79.89,48.76 79.89,49.1 79.77,49.22 79.54,49.22 79.43,49.1 79.43,48.76 79.31,48.64 79.09,48.64 78.97,48.76 78.97,49.1 78.86,49.22 78.63,49.22 78.51,49.1 78.51,48.76 78.4,48.64 78.17,48.64 78.06,48.76 78.06,49.1 77.94,49.22 77.71,49.22 77.6,49.1 77.6,48.76 77.49,48.64 77.26,48.64 77.14,48.76 77.14,49.1 77.03,49.22 76.8,49.22 76.69,49.1 76.69,48.76 76.57,48.64 76.34,48.64 76.23,48.76 76.23,49.1 76.11,49.22 75.89,49.22 75.77,49.1 75.77,48.76 75.66,48.64 75.43,48.64 75.31,48.76 75.31,49.1 75.2,49.22 74.34,49.22 v1(71.24,52.32)
QSPI_B_DATA6: length 27
  TOP w0.114: R360.1 v1(71.24,50.32) ; R391.1 85.72,45.04 v1(85.72,47.55)
  L3_IN1 w0.114: v1(85.72,47.55) 85.02,48.26 80.26,48.26 79.63,47.63 79.63,47.1 79.52,46.99 79.29,46.99 79.18,47.1 79.18,47.63 79.06,47.75 78.83,47.75 78.72,47.63 78.72,47.1 78.6,46.99 78.38,46.99 78.26,47.1 78.26,47.63 78.15,47.75 77.92,47.75 77.8,47.63 77.8,47.1 77.69,46.99 77.46,46.99 77.35,47.1 77.35,47.63 77.23,47.75 77,47.75 76.89,47.63 76.89,47.1 76.78,46.99 76.55,46.99 76.43,47.1 76.43,47.63 76.32,47.75 76.09,47.75 75.98,47.63 75.98,47.1 75.86,46.99 75.63,46.99 75.52,47.1 75.52,47.63 75.4,47.75 75.18,47.75 75.06,47.63 75.06,47.1 74.95,46.99 74.72,46.99 74.6,47.1 74.6,47.63 74.49,47.75 73.81,47.75 v1(71.24,50.32)
QSPI_B_DATA7: length 30.2
  TOP w0.114: R392.1 v1(98.35,45.85) ; R361.1 v1(71.29,49.32)
  L3_IN1 w0.114: v1(71.29,49.32) 74.34,46.26 97.94,46.26 v1(98.35,45.85)
QSPI_B_DQS: length 1.6
  TOP w0.114: TP44.1 R353.1
RESET_AMP: length 25.6
  TOP w0.152: v2(44.34,80.34) U12.E1 ; U17.E1 44.34,68.75 v2(44.33,68.76) 45.22,69.65 50.72,69.65 51.17,69.2 U16.4
  L4_IN2 w0.152: v2(44.34,80.34) 44.04,80.64 41.87,80.64 41.26,80.03 41.26,73.58 44.33,70.51 v2(44.33,68.76)
RESET_FXO: length 40.5
  TOP w0.114: v1(84.99,94.61) 85.02,94.64 R144.1 ; U30.4 v1(53.62,84.46)
  BOTTOM w0.114: v1(53.62,84.46) 56.68,84.46 58.2,85.98 58.2,90.62 58.84,91.26 62.14,91.26 62.98,92.1 82.48,92.1 v1(84.99,94.61)
RST_AP: length 4.4
  TOP w0.114: U108.A4 R242.1 77.53,53.32 R241.2
RST_MX: length 3
  TOP w0.114: R351.2 U19.A4
RTCXIN: length 6.6
  TOP w0.114: Y3.2 102.95,68.02 101.83,69.14 101.07,69.14 C69.1 99,68.63 98.89,68.52 U18.B17
RTCXOUT: length 6.9
  TOP w0.114: Y3.1 103,70.52 101.91,69.42 101.06,69.42 C62.1 99.66,69.02 U18.A17
SCL: length 52
  TOP w0.114: U18.E16 97.26,66.74 97.82,66.74 98.33,67.26 v1(104.94,67.26) TP30.1
  TOP w0.203: R84.2 125.7,48.69 v1(125.55,48.84) 125.43,48.97 124.19,48.97 123.96,49.2 U20.5
  BOTTOM w0.114: v1(125.55,48.84) 125.55,47.95 124.08,46.48 114.57,46.48 112.05,49 109.61,49 109.12,49.49 109.12,64.92 106.78,67.26 v1(104.94,67.26)
SCL_CODEC: length 16.4
  TOP w0.114: v1(49.81,100.09) R406.2 50.85,100.38 52.06,100.38 R411.2 U36.4
  TOP w0.152: v1(44.12,92.58) 44.12,93.64 43.76,94 U8.2
  L3_IN1 w0.114: v1(49.81,100.09) 49.26,100.09 44.12,94.96 v1(44.12,92.58)
SCLK_AP: length 7.4
  TOP w0.114: U108.B2 82.03,51.82 82.53,51.82 84.03,53.32 84.03,53.44 84.41,53.82 87.13,53.82 R245.2
SCLK_MX: length 3.8
  TOP w0.114: U19.B2 61.54,49.32 R352.2
SD_CLK: length 2
  TOP w0.114: J32.5 R302.1
SD_CMD: length 4.6
  TOP w0.114: J32.2 R303.1 126.92,32.25 125.6,33.57 R309.2
SD_DAT0: length 2.1
  TOP w0.114: J32.7 114.81,30.39 R301.1
SD_DAT1: length 2
  TOP w0.114: R300.1 112.95,32.24 J32.8
SD_DAT2: length 2
  TOP w0.114: J32.9 R305.1
SD_DAT3: length 2
  TOP w0.114: J32.1 R304.1
SD_RST_N: length 23.4
  TOP w0.114: R123.2 R90.1 U23.3 102.77,34.71 103.52,33.96 109.87,33.96 112.16,36.25 118.25,36.25 118.63,36.63 120.16,36.63 R306.1
SDA: length 56.5
  TOP w0.114: U18.F16 97.97,66.52 98.39,66.94 103.72,66.94 v1(104.05,66.62) 106.33,66.62 TP31.1
  TOP w0.203: R83.2 126.26,48.48 v1(126.26,48.84) 126.26,48.92 125.65,49.54 U20.6
  BOTTOM w0.114: v1(126.26,48.84) 126.26,47.72 124.21,45.67 114.34,45.67 111.6,48.4 109.37,48.4 108.77,49 108.77,64.55 106.7,66.62 v1(104.05,66.62)
SDA_CODEC: length 66.9
  TOP w0.114: R405.2 94.58,83 89.25,83 86.14,86.11 75.19,86.11 v1(74.57,86.73) ; v1(46.64,93.29) 46.11,92.76 R45.1 ; R412.2 57.81,99.85 v1(57.35,99.39) 56.89,99.85 U36.5
  L3_IN1 w0.114: v1(74.57,86.73) 74.57,86.61 74.06,86.1 68.09,86.1 66.6,87.59 66.6,93.47 60.68,99.39 v1(57.35,99.39) 56.9,98.93 49.49,98.93 47.64,97.08 47.64,94.29 v1(46.64,93.29)
SEL_ON_DMIC_1: length 6.7
  TOP w0.114: R377.2 9.38,2.83 8.79,3.42 7.5,3.42 7.3,3.63 7.3,5.01 7.62,5.33 8.38,5.33 8.6,5.11 U40.2
SEL_ON_DMIC_2: length 1.8
  TOP w0.114: R378.2 U41.2
SIO0_AP: length 4.5
  TOP w0.114: U108.D3 84.03,52.82 87.13,52.82 R243.1
SIO0_MX: length 4.4
  TOP w0.114: R354.2 69.05,52.83 66.05,52.83 U19.D3
SIO1_AP: length 4.5
  TOP w0.114: R417.1 87.13,51.82 84.03,51.82 U108.D2
SIO1_MX: length 3.2
  TOP w0.114: U19.D2 66.04,50.82 R355.2
SIO2_AP: length 3.4
  TOP w0.114: R418.1 82.03,55.8 82.03,53.82 U108.C4
SIO2_MX: length 3.4
  TOP w0.114: U19.C4 65.04,53.82 65.04,55.81 R356.2
SIO3_AP: length 3.4
  TOP w0.114: U108.D4 83.53,53.82 84.07,54.36 84.07,55.85 R419.1
SIO3_MX: length 3.4
  TOP w0.114: U19.D4 66.04,53.82 66.04,55.81 R357.2
SIO4_AP: length 2
  TOP w0.114: R244.1 U108.D5
SIO4_MX: length 2
  TOP w0.114: R358.2 U19.D5
SIO5_AP: length 3.1
  TOP w0.114: R420.1 U108.E3
SIO5_MX: length 3
  TOP w0.114: R359.2 U19.E3
SIO6_AP: length 3.5
  TOP w0.114: R421.1 86.63,51.32 U108.E2
SIO6_MX: length 3.4
  TOP w0.114: U19.E2 67.55,50.3 69.52,50.3 R360.2
SIO7_AP: length 3.5
  TOP w0.114: U108.E1 86.63,50.32 R422.1
SIO7_MX: length 3.4
  TOP w0.114: R361.2 67.54,49.32 U19.E1
SW1_OUT: length 47.4
  TOP w0.254: U20.19 121.17,51.95 120.65,52.47 v1(120.65,52.58)
  L3_IN1 w0.254: v1(120.65,52.58) 115.52,47.45 TP19.1
  BOTTOM w0.254: JP29.2 104.7,75.26 112.96,75.26 114.63,73.58 114.63,55.06 115.11,54.58 TP19.1
SW2_OUT: length 476.1
  TOP w0.114: U34.8 v1(43.2,82.85)
  TOP w0.229: C66.1 47.01,68.33 46.34,67.66 U17.A2 ; U12.A2 46.57,78.58 C46.1
  TOP w0.254: U34.1 47.24,83.39 v1(47.73,83.87) C331.1 ; U4.16 116.34,99.32 116.03,99.01 C22.2 ; Q16.2 v1(144.71,22.28)
  TOP w0.305: C139.2 115.01,95.71 U26.8 ; C37.2 117.76,89.01 U9.16
  TOP w0.381: U27.5 118.49,83.01 117.84,83.66 ; U28.1 117.82,86.53 118.11,86.23 118.11,83.93 117.84,83.66 ; U28.1 117.1,87.61 v1(117.5,88.01) C37.2 ; U28.1 116.39,86.53 116.04,86.88 C40.1 ; R407.1 v1(76.2,112.8) ; R408.1 41.16,56.76 v1(40.26,57.66) ; 117.84,83.66 U27.1 ; v1(144.8,28.03) Q15.2 R229.1 v1(144.8,26.84) ; v1(114.91,94.87) C139.2
  TOP w0.508: C46.1 v1(47.5,80.35) ; R128.1 v1(141.72,3.9) R131.1 ; R11.1 v1(50.65,112.92) ; R147.1 v1(115.67,92.66) ; JS2.2 48.43,104.41 JS3.2 ; JP12.1 91.3,79.44 C316.1 JP28.2 ; C40.1 v1(114.66,86.88) 114.64,86.89 R146.1 ; v1(134.24,59.05) 136.1,59.05 R86.1 R88.1 R87.1 ; 145.61,11.3 145.61,12.58 R372.1 v1(146.27,12.63) ; C22.2 v1(116,98.27) ; Q16.2 145.51,20.98 R228.1 ; C66.1 v1(48.01,69.03)
  L3_IN1 w0.508: v1(76.2,112.8) 74.65,111.25 74.65,106.83 88.9,92.58 88.9,91.19 91.69,88.39 106.33,88.39 v1(107.6,87.12) 104.05,83.57 98.68,83.57 97.97,82.85 JP12.1 ; v1(141.72,3.9) 145.29,7.47 145.29,11.64 v1(146.27,12.63) ; v1(47.5,80.35) 47.5,82.84 47.73,83.07 v1(47.73,83.87) ; v1(48.01,69.03) 48.01,65.28 45.44,62.71 45.44,58.88 44.22,57.66 v1(40.26,57.66) ; v1(115.67,92.66) 117.5,90.83 v1(117.5,88.01) 116.37,86.88 v1(114.66,86.88) ; v1(120.65,42.04) 121.41,41.27 121.41,33.91 119.38,31.88 83.44,31.88 80.26,35.05 73.69,35.05 v1(72.67,34.03)
  L4_IN2 w0.508: JP12.1 99.23,78.18 101.77,78.18 102.34,77.61 102.34,76.04 103,75.38 104.34,75.38 104.98,74.74 104.98,68.95 101.76,65.73 JP20.1 103,58.78 103,53.02 104.08,51.94 104.9,51.94 105.41,51.43 105.41,46.21 109.59,42.04 v1(120.65,42.04) 128.91,42.04 TP20.1 139.19,45.85 146.94,38.1 146.94,30.17 v1(144.8,28.03) ; v1(47.73,83.87) 45.16,83.87 40.26,88.77 40.26,93.51 46.74,99.99 46.74,102.68 JS3.2 ; v1(48.01,69.03) 48.01,79.84 v1(47.5,80.35)
  BOTTOM w0.508: v1(146.27,12.63) 144.71,14.19 v1(144.71,22.28) 145.92,23.5 145.92,25.72 v1(144.8,26.84) v1(144.8,28.03) ; JS12.2 72.41,40.43 72.41,34.28 v1(72.67,34.03) 73.11,34.47 R415.1 R416.1 ; JP25.1 JP10.1 81.27,72.85 82.12,73.7 84.46,73.7 88.14,77.38 91.07,77.38 JP28.2 ; v1(43.2,82.85) 44.22,83.87 v1(47.73,83.87) ; v1(115.67,92.66) 114.91,93.42 v1(114.91,94.87) 116.46,96.42 116.46,97.82 v1(116,98.27) ; JS3.2 48.45,110.72 v1(50.65,112.92) 51.68,111.89 75.29,111.89 v1(76.2,112.8) ; v1(107.6,87.12) 114.41,87.12 v1(114.66,86.88) ; v1(134.24,59.05) 132.72,57.53 TP20.1
SW2_OUT_MCU: length 9.3
  TOP w0.229: U18.F5 v2(91.97,66.52) ; U18.N10 v2(93.97,63.52) 93.22,63.52 92.97,63.27 U18.N8 v2(92.47,63.02) U18.N6 91.47,63.02 v2(91.47,63.02) 91.47,63.03 U18.M5 ; U18.K5 v2(91.97,64.52) v2(91.97,65.52) U18.H5
  BOTTOM w0.254: C116.1 92,64.55 v2(91.97,64.52) ; C120.1 v2(92.47,63.02) ; C121.1 v2(93.97,63.52) ; C122.1 v2(91.47,63.02) ; C111.1 v2(91.97,65.52)
SWDCLK_LINK2: length 14.6
  TOP w0.114: TP5.1 R8.1 141.73,112.12 132.8,112.12 U1.H2
SWDIO_LINK2: length 18.7
  TOP w0.114: TP4.1 141.4,115.52 v1(141.08,115.2)
  TOP w0.254: U1.C4 v3(131.22,107.33)
  BOTTOM w0.114: v3(131.22,107.33) 132.96,105.59 135.41,105.59 140.11,110.29 140.11,114.22 v1(141.08,115.2)
SYSRST_B: length 60
  TOP w0.114: U24.3 v1(142.48,16.71)
  TOP w0.203: R82.2 v1(126.55,52.37) 125.61,52.37 125.19,51.95 U20.11
  L4_IN2 w0.114: v1(126.55,52.37) 128.18,50.75 140.71,50.75 v1(142.96,52.99)
  BOTTOM w0.114: v1(142.48,16.71) 143.16,16.71 143.67,17.22 143.67,33.11 142.96,33.83 v1(142.96,52.99)
TCK_SWCLK: length 25.3
  TOP w0.114: U1.H10 125.53,112.22 117.86,112.22 116.84,111.21 116.84,109.48 v1(116.08,108.71) ; v1(112.06,107.06) 110.74,105.74 110.74,103.91 108.41,101.58 U3.2
  BOTTOM w0.114: v1(116.08,108.71) 113.72,108.71 v1(112.06,107.06)
TDO_SWO: length 38.8
  TOP w0.114: v1(115.87,110.18) 115.87,111.58 117.22,112.93 127.22,112.93 U1.J8 ; v1(107.52,99.36) 102.82,99.36 101.4,97.94 101.4,96.42 101.77,96.05 U5.3
  BOTTOM w0.114: v1(115.87,110.18) 113.61,110.18 111.23,107.8 111.23,103.07 v1(107.52,99.36)
TEMP_SEN: length 4.2
  TOP w0.203: v1(123.76,53.4) 123.56,53.19 U20.14
  BOTTOM w0.114: TP28.1 122.46,52.14 RT1.1 123.15,52.78 v1(123.76,53.4)
TMS_SWDIO: length 26
  TOP w0.114: U1.K4 129.6,114.54 115.27,114.54 108.7,107.98 U2.3
TMS_SWDIO_TXEN: length 32
  TOP w0.114: R20.1 105.61,106.71 U2.5 107.39,106.71 107.67,106.98 107.67,107.45 115.01,114.78 129.94,114.78 131.22,113.5 131.22,112.93 U1.J4
USB0_DM_TRGT: length 64.4
  TOP w0.114: J7.2 148.06,85.88 146.46,85.88 R222.2 145.82,86 144.04,86 U22.3 142.27,85.98 134.45,85.98 125.9,77.42 125.9,73.26 114.28,61.64 97.59,61.64 U18.T17
USB0_DP_TRGT: length 64.5
  TOP w0.114: U18.R17 97.61,61.88 114.18,61.88 125.65,73.36 125.65,77.52 134.35,86.22 142.26,86.22 U22.2 144,86.25 145.83,86.25 R221.2 146.66,86.16 148.03,86.16 J7.3
USB1_VDD3V3: length 27.8
  TOP w0.114: SH4.2 111.36,74.79 111.36,65.45 108.16,62.25 106.84,62.25 106.05,63.03 103.79,63.03 103.12,62.37 102.61,62.37 102.42,62.55 97.44,62.55 U18.N16
USB_DM_LINK: length 15.6
  TOP w0.114: 143.14,108.35 143.26,108.47 145.66,108.47 145.89,108.24 J5.2 ; 143.14,108.35 143.03,108.47 137.16,108.47 136.69,108.94 133.26,108.94 133.26,108.94 132.8,108.94 U1.E2 ; 143.14,108.35 U21.3
USB_DP_LINK: length 15.6
  TOP w0.114: U1.E1 133.36,109.18 133.81,109.18 133.91,109.28 133.91,109.32 134.01,109.42 134.15,109.42 134.25,109.32 134.25,109.28 134.35,109.18 134.49,109.18 134.59,109.28 134.59,109.53 134.69,109.63 134.84,109.63 134.94,109.53 134.94,109.28 135.04,109.18 136.79,109.18 137.26,108.71 143.03,108.71 143.14,108.82 ; 143.14,108.82 143.26,108.71 145.71,108.71 145.89,108.89 J5.3 ; 143.14,108.82 U21.2
USB_ID: length 3.4
  TOP w0.114: R14.2 U1.F1
USB_ID_LINK: length 9.4
  TOP w0.114: R14.1 145.65,110.13 146.24,109.54 J5.4
USB_VBUS_LINK: length 0.6
  TOP w0.254: U1.E3 v3(132.02,108.93)
  vias: v1(138.2,106.2) v1(138.2,105.28) v1(139.14,106.27) v1(139.57,105.23) v1(140.16,106.38)
USDHC_SPWR: length 139
  TOP w0.254: v1(122.08,29.03) 122.08,29.03 ; J45.74 77.33,31.91 v1(77.22,32.01) ; Y8.4 81.12,24.26 81.37,24 83.44,24 83.69,24.26 v1(83.69,27.94) ; J45.4 59.83,32.36 v1(59.84,32.38) ; J45.72 76.83,31.63 76.52,31.94 v1(76.52,32.38) ; v1(59.08,32) 59.33,31.75 J45.2
  TOP w0.508: R121.1 C89.1 118.22,37.65 JS14.1 ; C321.1 148.45,19.69 D26.C R224.2 149.88,20.83 150.39,21.34 150.39,25.36 R225.2 148.62,26.33 148.42,26.14 124.97,26.14 122.08,29.03 J32.4
  L4_IN2 w0.508: v1(122.08,29.03) 119.76,31.35 119.76,36.11 JS14.1
  BOTTOM w0.254: C251.1 76.45,32.45 v1(76.52,32.38)
  BOTTOM w0.508: v1(122.08,29.03) 120.99,27.94 v1(83.69,27.94) 80.78,30.85 C250.1 ; C250.1 77.37,31.87 v1(77.22,32.01) 76.85,32.38 v1(76.52,32.38) ; C250.1 75.84,30.85 74.57,29.58 R226.1 R227.1 63.01,29.58 62,30.6 C252.1 59.91,32.31 v1(59.84,32.38) 59.46,32.38 v1(59.08,32) 58.7,31.61 C253.1
V_LED: length 13.8
  TOP w0.254: R92.1 R96.1 R97.1 145.18,36.95 JS13.1
VMIDC: length 3.4
  TOP w0.203: U8.21 38.48,94.8 38.09,94.4
  TOP w0.381: C34.1 38.09,94.4
VREF_H: length 10.4
  TOP w0.203: U18.D2 89.77,67.32 88.06,67.32 C68.1
  TOP w0.254: C68.1 84.79,69.67 84.45,70.01 82.54,70.01 JP10.2
VREF_L: length 7.8
  TOP w0.203: 88.28,68.21 88.81,67.68 89.62,67.68 89.97,68.02 U18.C2
  TOP w0.254: JP9.1 84.79,71.28 C68.2 86.14,70.35 88.28,68.21
VSN_1: length 12.1
  TOP w0.114: U12.D6 44.74,76.38 43.6,75.24 34.29,75.24 R59.1
VSN_2: length 12.3
  TOP w0.152: U17.D6 44.74,65.41 42.96,63.63 R65.1
VSP_1: length 13.9
  TOP w0.114: R51.1 39.73,75.54 43.5,75.54 44.34,76.38 U12.E6
VSP_2: length 16.6
  TOP w0.152: R62.1 33.93,70.23 v1(35.36,68.81) ; U17.E6 44.34,65.52 42.82,64 36.63,64 v1(35.36,65.28)
  L3_IN1 w0.152: v1(35.36,68.81) 35.71,68.45 35.71,65.63 v1(35.36,65.28)
VSYS: length 23.3
  TOP w0.203: v1(121.19,53.67) 121.41,53.67 122.16,52.91 U20.17 ; v1(122.56,48.71) U20.2 ; 120.98,51.55 U20.20
  TOP w0.254: C87.1 123.35,47.92 v1(122.56,48.71) ; C79.1 120.36,54.5 v1(121.19,53.67) ; TP18.1 v1(113.41,55.88) ; 120.98,51.55 v1(120.65,51.55) 120.26,51.94 C81.1
  L3_IN1 w0.508: v1(113.41,55.88) 114.81,54.48 120.4,54.48 121.19,53.69 v1(121.19,53.67) 121.41,53.45 121.41,52.32 v1(120.65,51.55) 122.56,49.64 v1(122.56,48.71)
WL_REG_ON_3V3: length 79.6
  TOP w0.114: Q15.3 C320.1 ; v1(72.83,32.44) J45.56
  TOP w0.254: Q15.3 v1(136.78,30.15) ; v1(78.87,29.46) 73.17,29.46 72.83,29.8 J45.56
  L3_IN1 w0.254: v1(78.87,29.46) 79.76,30.35 136.58,30.35 v1(136.78,30.15)
  BOTTOM w0.102: R226.2 v1(72.83,32.44)
XTALIN: length 10.9
  TOP w0.114: U18.B14 95.97,69.75 96.85,70.63 98.73,70.63 98.95,70.85 C59.1 99.65,72.4 99.65,73.5 98.53,74.61 Y2.1 98.44,75.2 R56.1
XTALOUT: length 9.5
  TOP w0.114: R56.2 95.74,75.92 95.11,75.29 95.11,74.14 Y2.3 95.73,72.5 C58.1 95.73,70.43 95.81,70.35 95.81,69.89 95.74,69.83 95.74,68.8 U18.B13
N16965957: length 2.8
  TOP w0.203: U8.11 42,99.15 C19.1
N16965996: length 2.8
  TOP w0.203: U8.12 41.6,99.11 C18.1
N16974908: length 18.3
  BOTTOM w0.114: J36.1 7.37,36.07 9.14,34.29 R109.1
N16974910: length 21.2
  BOTTOM w0.114: J36.2 2.79,37.34 7.62,37.34 9.02,35.94 R108.2
N16974934: length 18.6
  BOTTOM w0.114: J36.3 6.6,30.99 R111.1
N16974944: length 21.5
  BOTTOM w0.114: J36.4 2.79,34.8 5.33,34.8 7.49,32.64 R110.2
N16974979: length 18.2
  BOTTOM w0.114: R112.1 6.86,29.34 5.21,30.99 J36.5
N16974981: length 21.4
  BOTTOM w0.114: R113.2 7.21,27.69 5.18,29.72 2.79,29.72 J36.6
N16975000: length 18.5
  BOTTOM w0.114: R114.1 8.05,26.04 5.64,28.45 J36.7
N16975002: length 21.7
  BOTTOM w0.114: J36.8 2.79,27.18 5.94,27.18 8.74,24.38 R115.2
N16975069: length 3
  BOTTOM w0.114: J35.1 5.13,41.99 R106.1
N17023483: length 1.1
  TOP w0.254: R96.2 147.98,43.56 D9.A
N17023485: length 1.1
  TOP w0.254: D8.A 147.99,49.91 R92.2
N17023487: length 1.1
  TOP w0.254: R97.2 149.1,38.73 D10.A
N17103807: length 2
  TOP w0.114: U9.13 115.47,91.55 R46.1
N17103888: length 23.1
  TOP w0.114: U9.9 117.76,93.68 117.64,93.79 113.6,93.79 JP4.2
  TOP w0.254: R23.1 116.34,104.9 U4.9 115.89,103.57 115.63,103.83 v1(115.63,104.17)
  L4_IN2 w0.114: v1(115.63,104.17) 113.56,102.1 113.56,93.75 JP4.2
N17103964: length 11
  TOP w0.114: U4.2 v1(118.8,100.6) 119.61,100.6 R37.2 ; U4.7 118.61,103.1 v1(118.62,103.1) ; U4.15 114.6,100.6 v1(114.43,100.43)
  BOTTOM w0.114: v1(118.62,103.1) 118.8,102.92 v1(118.8,100.6) 118.62,100.43 v1(114.43,100.43)
N17104052: length 2.2
  TOP w0.114: U4.5 118.77,102.1 119.02,102.36 R34.1
N17104054: length 2.1
  TOP w0.114: U4.12 113.29,102.1 R36.2
N17136364: length 5.8
  TOP w0.114: v1(135.87,111.24) 135.88,111.25 R13.1
  TOP w0.254: U1.F3 v3(132.02,110.53)
  BOTTOM w0.114: v1(135.87,111.24) 134.76,110.13 132.41,110.13 v3(132.02,110.53)
N17136422: length 8.4
  TOP w0.114: Y1.2 C13.1 135.51,104.64 U1.B1
N17136435: length 3
  TOP w0.114: U1.A6 129.22,103.18 R31.1
N17136473: length 3
  TOP w0.114: U1.A4 130.82,103.13 R32.2
N17136502: length 4.3
  TOP w0.114: R30.1 128.83,103.94 128.83,106.54 U1.B6
N17136518: length 17.3
  TOP w0.114: U1.C1 137.34,103.61 144.43,103.61 C14.2 145.01,103.01 Y1.1
N17202709: length 1.4
  TOP w0.152: R125.2 99.18,93.61 U7.8
N17202739: length 5.3
  TOP w0.114: JP3.1 94.56,98.37 R39.1 96.62,96.31 U7.2
N17208284: length 3.1
  TOP w0.114: U1.A10 126.02,105.01 125.73,104.72 R28.2
N17208314: length 5.9
  TOP w0.114: R5.1 v1(128.96,116.08)
  TOP w0.254: v3(127.19,112.18) 126.84,112.53 U1.J9
  BOTTOM w0.114: v1(128.96,116.08) 127.19,114.31 v3(127.19,112.18)
N17208318: length 5.2
  TOP w0.114: R15.1 122.73,109.98 122.99,109.73 126.42,109.73 U1.F9
N17208322: length 6.5
  TOP w0.114: v1(124.69,110.36) 122.81,110.36 R12.1
  TOP w0.254: U1.F8 v3(127.22,110.53)
  BOTTOM w0.114: v3(127.22,110.53) 126.76,110.07 124.98,110.07 v1(124.69,110.36)
N17208326: length 5.2
  TOP w0.114: U1.C9 126.42,108.13 122.48,108.13 R17.1
N17337786: length 2.9
  TOP w0.114: R35.1 101.21,101.58 U3.7
N17337788: length 3.4
  TOP w0.114: R35.2 99.52,102.28 JP18.2
N17337803: length 3.1
  TOP w0.114: U3.6 101.71,102.23 R26.1
N17337821: length 3.3
  TOP w0.114: U3.5 102.2,102.88 R24.1
N17337994: length 3.3
  TOP w0.114: U2.4 105.78,107.36 104.85,108.28 R18.1 R16.2
N17338012: length 6.1
  TOP w0.114: JP19.2 99.44,108.46 100.08,107.82 101.75,107.82 102.41,108.48 R18.2
N17338109: length 3.3
  TOP w0.114: R43.2 R44.1 103.34,92.06 U10.4
N17338127: length 4.8
  TOP w0.114: JP17.2 100.72,91.96 R44.2
N17340148: length 4.4
  TOP w0.762: D5.C 87.12,111.28 JP2.3
N17344064: length 2.3
  TOP w0.254: R7.2 D2.A
N17759955: length 3.3
  TOP w0.114: R72.2 J28.10
N17759973: length 3.3
  TOP w0.114: R73.2 J28.9
N17759990: length 132.9
  TOP w0.114: v1(135.93,11.38) 135.93,15.19 138.34,17.6 141.39,17.6 JP14.1
  L4_IN2 w0.114: J29.3 20.48,3.59 60.7,3.59 65.57,8.46 103.16,8.46 104.94,10.23 134.78,10.23 v1(135.93,11.38)
N17760012: length 3.3
  TOP w0.114: R74.2 J28.6
N17760030: length 3.1
  TOP w0.508: D12.C J29.5
N17760042: length 3.3
  TOP w0.114: R75.2 J28.5
N17760075: length 3.3
  TOP w0.114: R76.2 J28.4
N17760099: length 3.3
  TOP w0.114: R77.2 J28.3
N17760234: length 5.6
  TOP w0.114: J30.1 36.58,5.37 R99.1
N17760260: length 5.7
  TOP w0.114: R100.1 38.86,5.52 J30.2
N17760297: length 5.6
  TOP w0.114: J30.3 41.66,5.37 R101.1
N17760315: length 5.6
  TOP w0.114: R102.1 44.2,5.37 J30.4
N17760343: length 2.2
  TOP w0.114: R79.2 J27.2
N17760363: length 2.2
  TOP w0.114: R80.2 J27.1
N17774863: length 2.3
  TOP w0.114: R93.1 137.32,39.24 SW5.1
N17774865: length 2.3
  TOP w0.114: SW5.2 139.86,39.24 R94.1
N17774867: length 2.3
  TOP w0.114: SW5.3 142.4,39.24 R95.1
N17792148: length 2.6
  TOP w0.152: U8.3 43.88,94.4 44.96,93.32 R45.2
N17792155: length 3.2
  TOP w0.203: R48.2 44.35,91.36 43.38,92.34 U8.1
N17851401: length 31.9
  TOP w0.203: C6.1 30.07,111.91 30.07,87.96 33.4,84.63 R49.1
N17855943: length 10.6
  TOP w0.508: L5.1 v1(34.71,78.87)
  TOP w0.762: L5.1 R52.1
  BOTTOM w0.762: v2(42.7,77.76) v2(41.96,77.76) 35.81,77.76 v1(34.71,78.87)
N17855945: length 10.8
  TOP w0.508: L6.1 v1(34.71,77.34)
  TOP w0.762: R57.1 L6.1
  BOTTOM w0.762: v1(34.71,77.34) 36.09,75.96 v1(42.8,75.96)
N17886052: length 11.3
  TOP w0.762: R63.1 L9.1 v1(35.22,67.69) v1(36.17,67.69)
  BOTTOM w0.762: v1(35.22,67.69) v1(36.17,67.69) 37.02,66.84 v1(41.81,66.84) v1(42.6,66.84)
N17886097: length 10.7
  TOP w0.762: R64.1 L10.1 35.7,66.17 36.72,65.15 42.9,65.15
N18503998: length 2.3
  TOP w0.114: JS17.1 R134.2
N18526070: length 5.5
  TOP w0.254: R145.2 86.84,97.27 C24.1 85.49,98.63 U6.1
N18526135: length 4.9
  TOP w0.114: R117.2 86.84,101.34 SH3.1 86.76,100.13 U6.4
N18526137: length 7.4
  TOP w0.114: U6.6 82.29,101.72 84.4,103.84 SH2.1 86.83,103.83 R116.2
N18526318: length 2
  TOP w0.114: R40.2 JP30.2
N19506203: length 6.6
  TOP w0.152: R2.2 120.95,119.7 SW3.1
  TOP w0.254: SW3.2 SW3.1
N19508206: length 1.7
  TOP w0.254: R1.2 129.25,120.93 D1.A
N19508231: length 4.2
  TOP w0.152: Q8.2 126.7,118.01 128.05,119.37 D1.C
N19515078: length 1.1
  TOP w0.254: L1.1 144.81,105.64 C9.1
N19515258: length 5.4
  TOP w0.114: J7.4 147.46,87.01 146.98,87.49 TP38.1
N19519270: length 1.6
  TOP w0.203: R53.2 136.26,79.37 U13.A3
N19519289: length 7.2
  TOP w0.114: R60.1 134.94,73.43 Q1.3 134.92,75.82 U13.A1
N19526530: length 2.1
  TOP w0.114: R149.2 JP22.1
N19526548: length 2.1
  TOP w0.114: R61.1 JP22.3
N19527680: length 1.1
  TOP w0.508: R121.2 D15.A
N19531396: length 1.1
  TOP w0.254: R98.2 149.1,34.41 D11.A
N19546738: length 2
  TOP w0.114: TP43.1 R251.1
